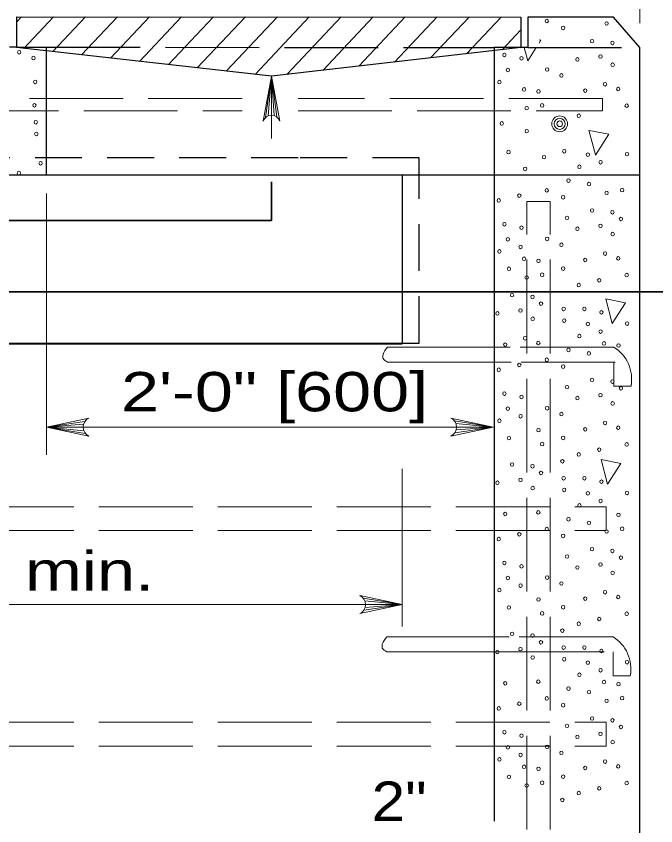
# Model space of a CAD drawing. Extents: x 1329.9 to 1363.9, y 715.5 to 737.5.
# Drawn here: x 1343.646 to 1346.184, y 730.9 to 734.111 of the extents above; entities that cross this region are included whole.
import ezdxf
from ezdxf.enums import TextEntityAlignment as Align

# ---------------------------------------------------------------- set-up
doc = ezdxf.new("R2010")
doc.units = 0
doc.header["$LTSCALE"] = 0.062
doc.linetypes.add('LONG_DASHED', pattern=[7.5, 6, -1.5])
doc.linetypes.add('MEDIUM_DASHED', pattern=[4.5, 3, -1.5])
doc.layers.add('1', color=7, linetype='Continuous', lineweight=13)

msp = doc.modelspace()

# ---------------------------------------------------------------- linework, layer by layer
at = {"layer": '1'}
for p, q in [((1346.12017, 734.08408), (1346.12017, 735.06533)), ((1343.64717, 734.08683), (1343.66792, 734.10883)), ((1343.67608, 733.98317), (1343.79475, 734.10875)), ((1343.79075, 733.97025), (1343.92167, 734.10875)), ((1343.90558, 733.95742), (1344.04833, 734.10858)), ((1344.02025, 733.94442), (1344.17525, 734.1085)), ((1344.13492, 733.93167), (1344.302, 734.1085)), ((1344.24958, 733.91875), (1344.42883, 734.10842)), ((1344.36433, 733.90583), (1344.55558, 734.10833)), ((1344.47908, 733.89292), (1344.68242, 734.10825)), ((1344.59375, 733.88), (1344.80925, 734.10825)), ((1344.72033, 733.87975), (1344.936, 734.10817)), ((1344.86267, 733.89608), (1345.06283, 734.108)), ((1345.005, 733.9125), (1345.18967, 734.108)), ((1345.14742, 733.92892), (1345.3165, 734.10792)), ((1345.28983, 733.94533), (1345.44333, 734.10783)), ((1345.43217, 733.96167), (1345.57008, 734.10775)), ((1345.5745, 733.97808), (1345.64867, 734.05658)), ((1345.64567, 733.98625), (1345.64867, 733.98942)), ((1344.63558, 733.7095), (1344.65908, 733.87267)), ((1344.64542, 733.71567), (1344.65908, 733.87267)), ((1344.65908, 733.71858), (1344.65908, 733.87267)), ((1344.66983, 733.71692), (1344.65908, 733.87267)), ((1344.68042, 733.71142), (1344.65908, 733.87267)), ((1344.65908, 733.87267), (1344.65908, 733.62658)), ((1345.97275, 733.7845), (1345.86917, 733.7845)), ((1345.97275, 733.73575), (1345.97275, 733.7845)), ((1345.97275, 733.73575), (1345.871, 733.73575)), ((1345.91833, 733.65858), (1345.944, 733.56125)), ((1345.99733, 733.64267), (1345.91942, 733.65783)), ((1345.94492, 733.5605), (1345.99717, 733.64267)), ((1343.76625, 733.40758), (1343.76625, 732.37083)), ((1345.60558, 732.798), (1345.11967, 732.798)), ((1345.11967, 732.73942), (1345.6105, 732.73942)), ((1343.91858, 732.50383), (1343.76625, 732.48125)), ((1343.91342, 732.49267), (1343.76625, 732.48125)), ((1345.38492, 732.50625), (1345.539, 732.48125)), ((1345.39075, 732.49575), (1345.539, 732.48125)), ((1343.76625, 732.48125), (1345.539, 732.48125)), ((1343.91183, 732.48125), (1343.76625, 732.48125)), ((1343.9145, 732.46683), (1343.76625, 732.48125)), ((1343.92033, 732.45633), (1343.76625, 732.48125)), ((1345.38675, 732.45875), (1345.539, 732.48125)), ((1345.39183, 732.46992), (1345.539, 732.48125)), ((1345.39342, 732.48125), (1345.539, 732.48125)), ((1345.1775, 732.31633), (1345.1775, 731.69)), ((1345.02342, 731.80233), (1345.1775, 731.77733)), ((1345.02925, 731.79183), (1345.1775, 731.77733)), ((1341.45675, 731.77733), (1345.1775, 731.77733)), ((1345.02525, 731.75483), (1345.1775, 731.77733)), ((1345.03042, 731.766), (1345.1775, 731.77733)), ((1345.03192, 731.77733), (1345.1775, 731.77733)), ((1345.60267, 731.64908), (1345.11667, 731.64908)), ((1345.11667, 731.5905), (1345.6075, 731.5905))]:
    msp.add_line(p, q, dxfattribs=at)
at = {"layer": '1', "lineweight": 25}
for p, q in [((1343.64717, 734.10883), (1345.64867, 734.10775)), ((1343.64717, 734.10883), (1343.64717, 733.98642)), ((1343.64817, 733.988), (1343.61975, 733.988)), ((1343.64817, 733.988), (1343.76625, 733.98792)), ((1343.76625, 733.48175), (1343.76625, 733.98792)), ((1345.54208, 733.98692), (1345.54208, 730.91825)), ((1345.67608, 733.98692), (1345.54208, 733.98692)), ((1346.12017, 729.46942), (1346.12017, 733.98667)), ((1341.09175, 733.48175), (1343.775, 733.48175)), ((1343.775, 733.48175), (1346.11958, 733.48175)), ((1345.1775, 733.48175), (1345.1775, 732.81183)), ((1341.406, 732.81483), (1345.24542, 732.81483)), ((1341.45675, 732.81183), (1345.1775, 732.81183))]:
    msp.add_line(p, q, dxfattribs=at)
at = {"layer": '1', "linetype": 'LONG_DASHED', "lineweight": 25}
for p, q in [((1343.76625, 733.98792), (1345.54208, 733.98692)), ((1345.67608, 733.98692), (1346.12017, 733.98667))]:
    msp.add_line(p, q, dxfattribs=at)
at = {"layer": '1', "linetype": 'LONG_DASHED'}
for p, q in [((1344.5425, 733.7845), (1340.61017, 733.7845)), ((1345.97275, 733.7845), (1344.76517, 733.7845)), ((1340.61017, 733.73575), (1344.5425, 733.73575)), ((1344.76517, 733.73575), (1345.97275, 733.73575)), ((1345.67267, 733.37567), (1345.76417, 733.37567)), ((1346.01717, 732.798), (1345.60558, 732.798)), ((1346.022, 732.73942), (1345.6105, 732.73942)), ((1340.67083, 732.1655), (1345.98667, 732.1655)), ((1345.98667, 732.1655), (1345.98667, 732.07058)), ((1340.67083, 732.07058), (1345.98667, 732.07058)), ((1346.01417, 731.64908), (1345.60267, 731.64908)), ((1340.67083, 731.31067), (1345.98667, 731.31067)), ((1345.98667, 731.31067), (1345.98667, 731.21567)), ((1340.67083, 731.21567), (1345.98667, 731.21567))]:
    msp.add_line(p, q, dxfattribs=at)
at = {"layer": '1', "linetype": 'MEDIUM_DASHED', "lineweight": 25}
for p, q in [((1344.76517, 733.54867), (1342.30275, 733.54867)), ((1345.24542, 733.54867), (1344.76517, 733.54867)), ((1345.24542, 732.81483), (1345.24542, 733.54867))]:
    msp.add_line(p, q, dxfattribs=at)
at = {"layer": '1', "lineweight": 35}
for p in [(1344.65908, 733.45467), (1343.146, 733.30067)]:
    msp.add_line(p, (1344.65908, 733.30067), dxfattribs=at)
at = {"layer": '1', "lineweight": 25}
for points in [[(1345.64867, 734.1075), (1345.64867, 733.98667), (1344.65908, 733.87267), (1343.64717, 733.98642)], [(1346.12017, 733.98667), (1346.01658, 734.1075), (1345.67608, 734.10767), (1345.67608, 733.98667)]]:
    msp.add_lwpolyline(points, dxfattribs=at)
at = {"layer": '1'}
for points in [[(1345.72042, 734.0045), (1345.72775, 734.01625), (1345.72042, 734.01758)], [(1345.66167, 733.98683), (1345.67558, 733.93408), (1345.70908, 733.98692)], [(1344.6255, 733.69458), (1344.65908, 733.87267), (1344.69275, 733.69458)], [(1343.9345, 732.44567), (1343.76625, 732.48125), (1343.9345, 732.51692)], [(1345.37075, 732.51692), (1345.539, 732.48125), (1345.37075, 732.44567)], [(1345.00933, 731.813), (1345.1775, 731.77733), (1345.00933, 731.74175)]]:
    msp.add_lwpolyline(points, dxfattribs=at)
at = {"layer": '1', "linetype": 'LONG_DASHED'}
for points in [[(1345.67267, 729.415), (1345.67267, 729.46942), (1345.67267, 733.37567)], [(1345.76417, 729.40517), (1345.76417, 729.46942), (1345.76417, 733.37567)], [(1346.01717, 732.73942), (1346.01717, 732.64375), (1346.0855, 732.64375)], [(1345.6075, 731.5905), (1346.01417, 731.5905), (1346.01417, 731.49475), (1346.0825, 731.49475)]]:
    msp.add_lwpolyline(points, dxfattribs=at)
at = {"layer": '1', "lineweight": 35}
msp.add_lwpolyline([(1340.12008, 733.01742), (1346.51367, 733.01742), (1346.51367, 732.60617)], dxfattribs=at)
at = {"layer": '1'}
for points in [[(1345.98517, 732.98942), (1346.01083, 732.89217), (1346.06308, 732.97433)], [(1345.96708, 732.35233), (1345.99275, 732.255), (1346.045, 732.33717)]]:
    msp.add_lwpolyline(points, close=True, dxfattribs=at)
for radius in [0.03133, 0.0219, 0.01122]:
    msp.add_circle((1345.8024, 733.68422), radius, dxfattribs=at)
for centre in [(1345.75101, 734.09184), (1345.81615, 734.06464), (1345.98854, 734.08216), (1345.93092, 734.01208), (1346.01175, 734.00509), (1343.65841, 733.96828), (1343.71492, 733.94472), (1345.58322, 733.95762), (1345.65083, 733.94402), (1345.87271, 733.93949), (1345.96433, 733.9513), (1345.59691, 733.89779), (1345.75276, 733.89958), (1346.0126, 733.91833), (1345.80927, 733.87602), (1343.7218, 733.85035), (1345.56344, 733.84971), (1345.98262, 733.84126), (1345.66114, 733.82072), (1345.7185, 733.81249), (1345.9038, 733.81591), (1346.03486, 733.82223), (1343.71868, 733.75761), (1345.67134, 733.74633), (1345.73304, 733.75725), (1346.06821, 733.75602), (1345.87805, 733.71611), (1343.72381, 733.6905), (1345.57255, 733.68583), (1343.72634, 733.64427), (1345.67165, 733.6551), (1345.82069, 733.57557), (1345.59948, 733.57193), (1345.74061, 733.55201), (1345.91411, 733.56197), (1346.06996, 733.56376), (1343.74321, 733.5279), (1345.88064, 733.51389), (1345.9646, 733.53202), (1343.65666, 733.48889), (1345.66542, 733.50544), (1345.83756, 733.45921), (1345.75101, 733.42019), (1345.91834, 733.44499), (1346.05024, 733.42143), (1345.64227, 733.39932), (1345.81615, 733.39299), (1345.98854, 733.41051), (1345.56085, 733.38029), (1345.93092, 733.34044), (1346.01175, 733.33344), (1345.58322, 733.28598), (1345.83158, 733.31139), (1346.04543, 733.30685), (1345.65083, 733.27238), (1345.87271, 733.26784), (1345.96433, 733.27965), (1345.59691, 733.22614), (1345.75276, 733.22794), (1346.0126, 733.24669), (1345.6474, 733.1962), (1345.80927, 733.20437), (1345.56344, 733.17807), (1345.98262, 733.16961), (1345.66114, 733.14907), (1345.7185, 733.14085), (1345.9038, 733.14426), (1346.03486, 733.15058), (1345.60114, 733.10917), (1345.81615, 733.11001), (1345.67134, 733.07469), (1345.73304, 733.0856), (1345.95947, 733.06349), (1346.06821, 733.08437), (1345.87805, 733.04446), (1345.61372, 733.00461), (1345.69455, 732.99762), (1345.72823, 732.97103), (1345.64713, 732.94383), (1345.81816, 732.95015), (1345.90042, 732.95015), (1345.96803, 732.93655), (1345.55551, 732.93202), (1345.6954, 732.91086), (1345.82069, 732.90392), (1345.91411, 732.89032), (1346.06996, 732.89211), (1345.88064, 732.84224), (1345.9646, 732.86038), (1345.5866, 732.80844), (1345.66542, 732.83379), (1345.71766, 732.81476), (1345.97834, 732.81325), (1346.0357, 732.80502), (1345.83756, 732.78756), (1345.91834, 732.77334), (1345.75101, 732.74855), (1345.56085, 732.70864), (1345.64227, 732.72767), (1345.81615, 732.72135), (1345.93092, 732.66879), (1346.01175, 732.66179), (1345.58322, 732.61433), (1345.83158, 732.63974), (1346.04543, 732.63521), (1345.65083, 732.60073), (1345.87271, 732.5962), (1345.96433, 732.60801), (1345.59691, 732.5545), (1345.75276, 732.55629), (1346.0126, 732.57504), (1345.6474, 732.52455), (1345.80927, 732.53273), (1345.56344, 732.50642), (1345.98262, 732.49797), (1345.7185, 732.4692), (1345.9038, 732.47261), (1346.03486, 732.47894), (1345.60114, 732.43752), (1345.81615, 732.43836), (1345.73304, 732.41396), (1345.95947, 732.39185), (1346.06821, 732.41273), (1345.87805, 732.37282), (1345.61372, 732.33297), (1345.69455, 732.32597), (1345.81303, 732.34562), (1345.72823, 732.29939), (1345.55551, 732.26037), (1345.64713, 732.27218), (1345.81816, 732.27851), (1345.90042, 732.27851), (1345.96803, 732.26491), (1345.6954, 732.23922), (1345.82069, 732.23228), (1345.91411, 732.21868), (1346.06996, 732.22047), (1345.88064, 732.1706), (1345.9646, 732.18873), (1345.5866, 732.13679), (1345.71766, 732.14312), (1346.0357, 732.13338), (1345.83756, 732.11591), (1345.91834, 732.1017), (1345.75101, 732.0769), (1345.98854, 732.06722), (1346.05024, 732.07813), (1345.56085, 732.037), (1345.64227, 732.05603), (1345.81615, 732.0497), (1345.93092, 731.99715), (1346.01175, 731.99015), (1345.58322, 731.94269), (1345.83158, 731.9681), (1346.04543, 731.96356), (1345.65083, 731.92909), (1345.87271, 731.92455), (1345.96433, 731.93636), (1345.59691, 731.88285), (1345.75276, 731.88464), (1346.0126, 731.90339), (1345.6474, 731.85291), (1345.80927, 731.86108), (1345.56344, 731.83477), (1345.98262, 731.82632), (1345.7185, 731.79755), (1345.9038, 731.80097), (1346.03486, 731.80729), (1345.60114, 731.76588), (1345.81615, 731.76671), (1345.73304, 731.74231), (1345.95947, 731.7202), (1346.06821, 731.74108), (1345.87805, 731.70117), (1345.61372, 731.66132), (1345.69455, 731.65433), (1345.81303, 731.67397), (1345.72823, 731.62774), (1345.55551, 731.58873), (1345.64713, 731.60054), (1345.81816, 731.60686), (1345.90042, 731.60686), (1345.96803, 731.59326), (1345.6954, 731.56757), (1345.82069, 731.56063), (1345.91411, 731.54703), (1346.06996, 731.54882), (1345.88064, 731.49895), (1345.9646, 731.51709), (1345.5866, 731.46515), (1345.71766, 731.47147), (1345.97834, 731.46996), (1346.0357, 731.46173), (1345.83756, 731.44427), (1345.91834, 731.43005), (1345.75101, 731.40526), (1345.98854, 731.39557), (1346.05024, 731.40649), (1345.56085, 731.36535), (1345.64227, 731.38438), (1345.81615, 731.37806), (1345.83158, 731.29645), (1345.93092, 731.3255), (1346.01175, 731.3185), (1345.58322, 731.27104), (1345.96433, 731.26472), (1346.04543, 731.29192), (1345.65083, 731.25744), (1345.87271, 731.25291), (1346.0126, 731.23175), (1345.59691, 731.21121), (1345.75276, 731.213), (1345.6474, 731.18126), (1345.80927, 731.18944), (1345.56344, 731.16313), (1345.66114, 731.13414), (1345.98262, 731.15468), (1346.03486, 731.13565), (1345.7185, 731.12591), (1345.9038, 731.12932), (1345.60114, 731.09423), (1345.73304, 731.07067), (1345.81615, 731.09507), (1345.67134, 731.05975), (1345.95947, 731.04856), (1346.06821, 731.06943), (1345.87805, 731.02953), (1345.81303, 731.00233)]:
    msp.add_ellipse(centre, major_axis=(0, 0.00718), ratio=0.944544, dxfattribs=at)
for centre, major_axis, start_param, end_param in [((1344.6591, 733.68011), (0, 0.03844), 5.0978942, 7.4685073), ((1343.94814, 732.48129), (0, 0.03844), 0.3855052, 2.7561184), ((1345.35713, 732.48128), (0, -0.03844), 0.3855052, 2.7561184), ((1344.99565, 731.77736), (0, -0.03844), 0.3855052, 2.7561184)]:
    msp.add_ellipse(centre, major_axis=major_axis, ratio=0.944544, start_param=start_param, end_param=end_param, dxfattribs=at)
at = {"layer": '1', "linetype": 'LONG_DASHED'}
for centre in [(1345.9509, 732.67098), (1345.94791, 731.52206)]:
    msp.add_ellipse(centre, major_axis=(0, -0.14504), ratio=0.944544, start_param=1.3817766, end_param=2.6372404, dxfattribs=at)
at = {"layer": '1'}
for points in [[(1345.11967, 732.798), (1345.10175, 732.76892), (1345.10175, 732.7535), (1345.11967, 732.73942)], [(1345.11667, 731.64908), (1345.09883, 731.62), (1345.09883, 731.60458), (1345.11667, 731.5905)]]:
    msp.add_spline(points, degree=3, dxfattribs=at)

# ---------------------------------------------------------------- texts
for s, width, p in [('2\'-0" [600]', 1.3, (1344.67142, 732.54383)), ('2"', 1.15, (1345.16538, 730.9195))]:
    msp.add_text(s, height=0.156, dxfattribs=dict(at, width=width)).set_placement(p, align=Align.CENTER)
at = {"layer": '1', "width": 1.3}
msp.add_text('48" [1200] min.', height=0.156, dxfattribs=at).set_placement((1342.3785, 731.83267))

doc.saveas('drawing.dxf')
